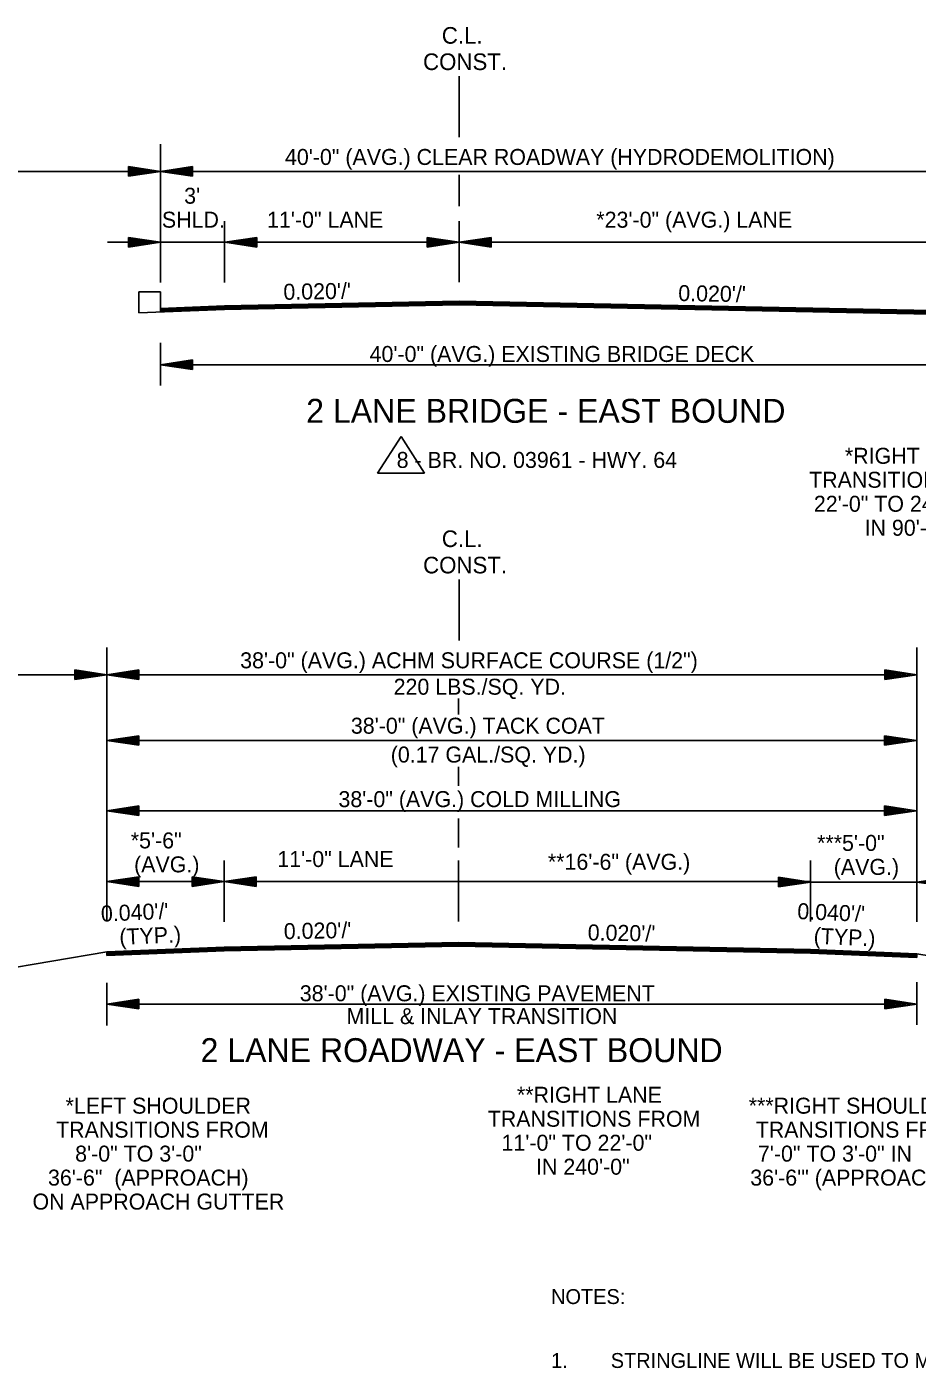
# Model space of a CAD drawing. Extents: x 542112 to 1930787, y -1968972 to 596640.
# Drawn here: x 545011 to 545428, y -1951935 to -1951306 of the extents above; entities that cross this region are included whole.
import ezdxf

# ---------------------------------------------------------------- set-up
doc = ezdxf.new("R2010")
doc.units = 0
for name, color, linetype in [('R_Border', 7, 'Continuous'), ('R_Border Notes', 7, 'Continuous'), ('R_Draft', 7, 'Continuous')]:
    doc.layers.add(name, color=color, linetype=linetype)

msp = doc.modelspace()

# ---------------------------------------------------------------- linework, layer by layer
at = {"layer": 'R_Border'}
for p, q in [((545073.38, -1951430.3), (545063.21, -1951430.3)), ((545063.21, -1951430.3), (545063.21, -1951440.11)), ((545073.38, -1951439.73), (545073.38, -1951430.3)), ((545186.15, -1951498.09), (545175.11, -1951515.4)), ((545197.19, -1951515.4), (545186.15, -1951498.09)), ((545175.11, -1951515.4), (545197.19, -1951515.4))]:
    msp.add_line(p, q, dxfattribs=at)
at = {"layer": 'R_Draft'}
for p, q in [((545213.38, -1951357.67), (545213.38, -1951329.02)), ((545073.38, -1951360.97), (545073.38, -1951425.86)), ((544727.98, -1951373.73), (545073.38, -1951373.73)), ((545058.38, -1951371.48), (545073.38, -1951373.73)), ((545058.38, -1951371.48), (545058.38, -1951375.98)), ((545058.38, -1951371.86), (545070.87, -1951373.73)), ((545058.38, -1951372.24), (545068.29, -1951373.73)), ((545058.38, -1951372.61), (545065.8, -1951373.73)), ((545058.38, -1951373), (545063.25, -1951373.73)), ((545058.38, -1951373.38), (545060.75, -1951373.73)), ((545058.38, -1951375.98), (545073.38, -1951373.73)), ((545058.38, -1951374.47), (545063.25, -1951373.73)), ((545058.38, -1951375.22), (545068.29, -1951373.73)), ((545058.38, -1951375.61), (545070.87, -1951373.73)), ((545058.38, -1951374.85), (545065.8, -1951373.73)), ((545058.38, -1951374.08), (545060.75, -1951373.73)), ((545088.38, -1951371.48), (545073.38, -1951373.73)), ((545088.38, -1951375.98), (545073.38, -1951373.73)), ((545073.38, -1951373.73), (545473.38, -1951373.73)), ((545088.38, -1951371.86), (545075.88, -1951373.73)), ((545088.38, -1951375.61), (545075.88, -1951373.73)), ((545088.38, -1951372.24), (545078.46, -1951373.73)), ((545088.38, -1951375.22), (545078.46, -1951373.73)), ((545088.38, -1951372.61), (545080.96, -1951373.73)), ((545088.38, -1951374.85), (545080.96, -1951373.73)), ((545088.38, -1951373), (545083.5, -1951373.73)), ((545088.38, -1951374.46), (545083.5, -1951373.73)), ((545088.38, -1951373.38), (545086.01, -1951373.73)), ((545088.38, -1951374.08), (545086.01, -1951373.73)), ((545088.38, -1951375.98), (545088.38, -1951371.48)), ((545213.38, -1951390.12), (545213.38, -1951375.32)), ((545103.38, -1951425.86), (545103.38, -1951397.13)), ((545213.38, -1951425.69), (545213.38, -1951397.13)), ((545103.38, -1951407.03), (545048.38, -1951407.03)), ((545058.38, -1951404.78), (545073.38, -1951407.03)), ((545058.38, -1951404.78), (545058.38, -1951409.28)), ((545058.38, -1951405.15), (545070.87, -1951407.03)), ((545058.38, -1951405.53), (545068.29, -1951407.03)), ((545058.38, -1951405.91), (545065.8, -1951407.03)), ((545058.38, -1951406.3), (545063.25, -1951407.03)), ((545058.38, -1951406.67), (545060.75, -1951407.03)), ((545058.38, -1951409.28), (545073.38, -1951407.03)), ((545058.38, -1951407.76), (545063.25, -1951407.03)), ((545058.38, -1951408.52), (545068.29, -1951407.03)), ((545058.38, -1951408.9), (545070.87, -1951407.03)), ((545058.38, -1951408.14), (545065.8, -1951407.03)), ((545058.38, -1951407.38), (545060.75, -1951407.03)), ((545213.38, -1951407.03), (545103.38, -1951407.03)), ((545118.5, -1951404.78), (545103.5, -1951407.03)), ((545118.5, -1951409.28), (545103.5, -1951407.03)), ((545118.5, -1951405.15), (545106.01, -1951407.03)), ((545118.5, -1951408.9), (545106.01, -1951407.03)), ((545118.5, -1951405.53), (545108.59, -1951407.03)), ((545118.5, -1951408.52), (545108.59, -1951407.03)), ((545118.5, -1951405.91), (545111.09, -1951407.03)), ((545118.5, -1951408.14), (545111.09, -1951407.03)), ((545118.5, -1951406.29), (545113.63, -1951407.03)), ((545118.5, -1951407.75), (545113.63, -1951407.03)), ((545118.5, -1951406.67), (545116.13, -1951407.03)), ((545118.5, -1951407.38), (545116.13, -1951407.03)), ((545118.5, -1951409.28), (545118.5, -1951404.78)), ((545198.38, -1951404.78), (545213.38, -1951407.03)), ((545198.38, -1951404.78), (545198.38, -1951409.28)), ((545198.38, -1951405.15), (545210.87, -1951407.03)), ((545198.38, -1951405.53), (545208.29, -1951407.03)), ((545198.38, -1951405.91), (545205.8, -1951407.03)), ((545198.38, -1951406.3), (545203.25, -1951407.03)), ((545198.38, -1951406.67), (545200.75, -1951407.03)), ((545198.38, -1951409.28), (545213.38, -1951407.03)), ((545198.38, -1951407.76), (545203.25, -1951407.03)), ((545198.38, -1951408.52), (545208.29, -1951407.03)), ((545198.38, -1951408.9), (545210.87, -1951407.03)), ((545198.38, -1951408.14), (545205.8, -1951407.03)), ((545198.38, -1951407.38), (545200.75, -1951407.03)), ((545228.38, -1951404.78), (545213.38, -1951407.03)), ((545443.38, -1951407.03), (545213.38, -1951407.03)), ((545228.38, -1951409.28), (545213.38, -1951407.03)), ((545228.38, -1951405.15), (545215.88, -1951407.03)), ((545228.38, -1951408.9), (545215.88, -1951407.03)), ((545228.38, -1951405.53), (545218.46, -1951407.03)), ((545228.38, -1951408.52), (545218.46, -1951407.03)), ((545228.38, -1951405.91), (545220.96, -1951407.03)), ((545228.38, -1951408.14), (545220.96, -1951407.03)), ((545228.38, -1951406.29), (545223.5, -1951407.03)), ((545228.38, -1951407.75), (545223.5, -1951407.03)), ((545228.38, -1951406.67), (545226.01, -1951407.03)), ((545228.38, -1951407.38), (545226.01, -1951407.03)), ((545228.38, -1951409.28), (545228.38, -1951404.78)), ((545103.38, -1951438.5), (545063.21, -1951440.11)), ((545103.38, -1951436.83), (545073.38, -1951438.03)), ((545103.38, -1951437.13), (545073.38, -1951438.33)), ((545103.38, -1951437.43), (545073.38, -1951438.63)), ((545103.38, -1951437.73), (545073.38, -1951438.93)), ((545103.38, -1951438.03), (545073.38, -1951439.23)), ((545103.38, -1951438.33), (545073.38, -1951439.53)), ((545213.38, -1951434.63), (545103.38, -1951436.83)), ((545213.38, -1951434.93), (545103.38, -1951437.13)), ((545213.38, -1951435.23), (545103.38, -1951437.43)), ((545213.38, -1951435.53), (545103.38, -1951437.73)), ((545213.38, -1951435.83), (545103.38, -1951438.03)), ((545213.38, -1951436.13), (545103.38, -1951438.33)), ((545213.38, -1951436.3), (545103.38, -1951438.5)), ((545213.38, -1951434.63), (545453.31, -1951439.43)), ((545213.38, -1951434.93), (545453.31, -1951439.73)), ((545213.38, -1951435.23), (545453.31, -1951440.03)), ((545213.38, -1951435.53), (545453.31, -1951440.33)), ((545213.38, -1951435.83), (545453.31, -1951440.63)), ((545213.38, -1951436.13), (545453.31, -1951440.93)), ((545213.38, -1951436.3), (545453.31, -1951441.1)), ((545073.38, -1951454.24), (545073.38, -1951474.24)), ((545088.37, -1951462.24), (545073.37, -1951464.49)), ((545088.37, -1951462.62), (545075.87, -1951464.49)), ((545088.37, -1951463), (545078.45, -1951464.49)), ((545088.37, -1951463.37), (545080.95, -1951464.49)), ((545088.37, -1951463.76), (545083.49, -1951464.49)), ((545088.37, -1951466.74), (545088.37, -1951462.24)), ((545088.37, -1951466.74), (545073.37, -1951464.49)), ((545073.38, -1951464.49), (545473.31, -1951464.49)), ((545088.37, -1951466.37), (545075.87, -1951464.49)), ((545088.37, -1951465.98), (545078.45, -1951464.49)), ((545088.37, -1951465.61), (545080.95, -1951464.49)), ((545088.37, -1951465.22), (545083.49, -1951464.49)), ((545088.37, -1951464.14), (545086, -1951464.49)), ((545088.37, -1951464.84), (545086, -1951464.49)), ((545213.38, -1951593.87), (545213.38, -1951565.22)), ((545048.18, -1951597.18), (545048.18, -1951725.69)), ((545428.18, -1951597.18), (545428.18, -1951725.86)), ((545033.18, -1951607.68), (545048.18, -1951609.93)), ((545033.18, -1951607.68), (545033.18, -1951612.18)), ((545033.18, -1951607.68), (545048.18, -1951609.93)), ((545033.18, -1951607.68), (545033.18, -1951612.18)), ((545033.18, -1951608.06), (545045.67, -1951609.93)), ((545033.18, -1951608.06), (545045.67, -1951609.93)), ((545033.18, -1951608.44), (545043.09, -1951609.93)), ((545033.18, -1951608.44), (545043.09, -1951609.93)), ((545063.18, -1951607.68), (545048.18, -1951609.93)), ((545063.18, -1951608.06), (545050.68, -1951609.93)), ((545063.18, -1951608.44), (545053.26, -1951609.93)), ((545063.18, -1951607.68), (545063.18, -1951612.18)), ((545413.18, -1951607.68), (545428.18, -1951609.93)), ((545413.18, -1951612.18), (545413.18, -1951607.68)), ((545413.18, -1951608.06), (545425.67, -1951609.93)), ((545413.18, -1951608.44), (545423.09, -1951609.93)), ((544778.18, -1951609.93), (545048.18, -1951609.93)), ((545033.18, -1951608.82), (545040.6, -1951609.93)), ((545033.18, -1951608.82), (545040.6, -1951609.93)), ((545033.18, -1951609.21), (545038.05, -1951609.93)), ((545033.18, -1951609.21), (545038.05, -1951609.93)), ((545033.18, -1951609.58), (545035.55, -1951609.93)), ((545033.18, -1951609.58), (545035.55, -1951609.93)), ((545033.18, -1951612.18), (545048.18, -1951609.93)), ((545033.18, -1951610.67), (545038.05, -1951609.93)), ((545033.18, -1951611.43), (545043.09, -1951609.93)), ((545033.18, -1951611.81), (545045.67, -1951609.93)), ((545033.18, -1951611.05), (545040.6, -1951609.93)), ((545033.18, -1951610.29), (545035.55, -1951609.93)), ((545033.18, -1951612.18), (545048.18, -1951609.93)), ((545033.18, -1951610.67), (545038.05, -1951609.93)), ((545033.18, -1951611.43), (545043.09, -1951609.93)), ((545033.18, -1951611.81), (545045.67, -1951609.93)), ((545033.18, -1951611.05), (545040.6, -1951609.93)), ((545033.18, -1951610.29), (545035.55, -1951609.93)), ((545418.18, -1951609.93), (545048.18, -1951609.93)), ((545063.18, -1951612.18), (545048.18, -1951609.93)), ((545063.18, -1951611.81), (545050.68, -1951609.93)), ((545063.18, -1951611.43), (545053.26, -1951609.93)), ((545063.18, -1951608.82), (545055.76, -1951609.93)), ((545063.18, -1951611.05), (545055.76, -1951609.93)), ((545063.18, -1951609.21), (545058.3, -1951609.93)), ((545063.18, -1951610.67), (545058.3, -1951609.93)), ((545063.18, -1951609.58), (545060.81, -1951609.93)), ((545063.18, -1951610.29), (545060.81, -1951609.93)), ((545413.18, -1951608.82), (545420.6, -1951609.93)), ((545413.18, -1951609.2), (545418.05, -1951609.93)), ((545413.18, -1951609.58), (545415.55, -1951609.93)), ((545413.18, -1951612.18), (545428.18, -1951609.93)), ((545413.18, -1951610.66), (545418.05, -1951609.93)), ((545413.18, -1951611.43), (545423.09, -1951609.93)), ((545413.18, -1951611.81), (545425.67, -1951609.93)), ((545413.18, -1951611.05), (545420.6, -1951609.93)), ((545413.18, -1951610.29), (545415.55, -1951609.93)), ((545213.18, -1951621.16), (545213.18, -1951628.53)), ((545063.18, -1951638.55), (545048.18, -1951640.8)), ((545063.18, -1951638.93), (545050.68, -1951640.8)), ((545063.18, -1951639.31), (545053.26, -1951640.8)), ((545063.18, -1951639.68), (545055.76, -1951640.8)), ((545063.18, -1951640.07), (545058.3, -1951640.8)), ((545063.18, -1951643.05), (545063.18, -1951638.55)), ((545412.98, -1951638.55), (545427.98, -1951640.8)), ((545412.98, -1951638.55), (545412.98, -1951643.05)), ((545412.98, -1951638.93), (545425.47, -1951640.8)), ((545412.98, -1951639.31), (545422.89, -1951640.8)), ((545412.98, -1951639.68), (545420.4, -1951640.8)), ((545412.98, -1951640.07), (545417.85, -1951640.8)), ((545418.18, -1951640.8), (545048.18, -1951640.8)), ((545063.18, -1951643.05), (545048.18, -1951640.8)), ((545063.18, -1951642.68), (545050.68, -1951640.8)), ((545063.18, -1951642.29), (545053.26, -1951640.8)), ((545063.18, -1951641.92), (545055.76, -1951640.8)), ((545063.18, -1951641.53), (545058.3, -1951640.8)), ((545063.18, -1951640.45), (545060.81, -1951640.8)), ((545063.18, -1951641.15), (545060.81, -1951640.8)), ((545412.98, -1951640.45), (545415.35, -1951640.8)), ((545412.98, -1951643.05), (545427.98, -1951640.8)), ((545412.98, -1951641.54), (545417.85, -1951640.8)), ((545412.98, -1951642.29), (545422.89, -1951640.8)), ((545412.98, -1951642.68), (545425.47, -1951640.8)), ((545412.98, -1951641.92), (545420.4, -1951640.8)), ((545412.98, -1951641.15), (545415.35, -1951640.8)), ((545213.18, -1951653.15), (545213.18, -1951662.11)), ((545063.18, -1951671.48), (545048.18, -1951673.73)), ((545063.18, -1951675.98), (545063.18, -1951671.48)), ((545412.98, -1951671.48), (545427.98, -1951673.73)), ((545412.98, -1951671.48), (545412.98, -1951675.98)), ((545063.18, -1951675.98), (545048.18, -1951673.73)), ((545418.18, -1951673.73), (545048.18, -1951673.73)), ((545063.18, -1951671.86), (545050.68, -1951673.73)), ((545063.18, -1951675.61), (545050.68, -1951673.73)), ((545063.18, -1951672.24), (545053.26, -1951673.73)), ((545063.18, -1951675.22), (545053.26, -1951673.73)), ((545063.18, -1951672.61), (545055.76, -1951673.73)), ((545063.18, -1951674.85), (545055.76, -1951673.73)), ((545063.18, -1951673), (545058.3, -1951673.73)), ((545063.18, -1951674.46), (545058.3, -1951673.73)), ((545063.18, -1951673.38), (545060.81, -1951673.73)), ((545063.18, -1951674.08), (545060.81, -1951673.73)), ((545213.18, -1951677.36), (545213.18, -1951691)), ((545412.98, -1951671.86), (545425.47, -1951673.73)), ((545412.98, -1951672.24), (545422.89, -1951673.73)), ((545412.98, -1951672.61), (545420.4, -1951673.73)), ((545412.98, -1951673), (545417.85, -1951673.73)), ((545412.98, -1951673.38), (545415.35, -1951673.73)), ((545412.98, -1951675.98), (545427.98, -1951673.73)), ((545412.98, -1951674.47), (545417.85, -1951673.73)), ((545412.98, -1951675.22), (545422.89, -1951673.73)), ((545412.98, -1951675.61), (545425.47, -1951673.73)), ((545412.98, -1951674.85), (545420.4, -1951673.73)), ((545412.98, -1951674.08), (545415.35, -1951673.73)), ((545103.18, -1951725.86), (545103.18, -1951697.13)), ((545213.18, -1951725.69), (545213.18, -1951697.13)), ((545378.18, -1951725.69), (545378.18, -1951697.13)), ((545063.18, -1951704.78), (545048.18, -1951707.03)), ((545103.18, -1951707.03), (545048.18, -1951707.03)), ((545063.18, -1951709.28), (545048.18, -1951707.03)), ((545063.18, -1951705.15), (545050.68, -1951707.03)), ((545063.18, -1951708.9), (545050.68, -1951707.03)), ((545063.18, -1951705.53), (545053.26, -1951707.03)), ((545063.18, -1951708.52), (545053.26, -1951707.03)), ((545063.18, -1951705.91), (545055.76, -1951707.03)), ((545063.18, -1951708.14), (545055.76, -1951707.03)), ((545063.18, -1951706.29), (545058.3, -1951707.03)), ((545063.18, -1951707.75), (545058.3, -1951707.03)), ((545063.18, -1951706.67), (545060.81, -1951707.03)), ((545063.18, -1951707.38), (545060.81, -1951707.03)), ((545063.18, -1951709.28), (545063.18, -1951704.78)), ((545088.18, -1951704.78), (545103.18, -1951707.03)), ((545088.18, -1951704.78), (545088.18, -1951709.28)), ((545088.18, -1951705.15), (545100.67, -1951707.03)), ((545088.18, -1951705.53), (545098.09, -1951707.03)), ((545088.18, -1951705.91), (545095.6, -1951707.03)), ((545088.18, -1951706.3), (545093.05, -1951707.03)), ((545088.18, -1951706.67), (545090.55, -1951707.03)), ((545088.18, -1951709.28), (545103.18, -1951707.03)), ((545088.18, -1951707.76), (545093.05, -1951707.03)), ((545088.18, -1951708.52), (545098.09, -1951707.03)), ((545088.18, -1951708.9), (545100.67, -1951707.03)), ((545088.18, -1951708.14), (545095.6, -1951707.03)), ((545088.18, -1951707.38), (545090.55, -1951707.03)), ((545118.18, -1951704.78), (545103.18, -1951707.03)), ((545213.18, -1951707.03), (545103.18, -1951707.03)), ((545118.18, -1951709.28), (545103.18, -1951707.03)), ((545118.18, -1951705.15), (545105.68, -1951707.03)), ((545118.18, -1951708.9), (545105.68, -1951707.03)), ((545118.18, -1951705.53), (545108.26, -1951707.03)), ((545118.18, -1951708.52), (545108.26, -1951707.03)), ((545118.18, -1951705.91), (545110.76, -1951707.03)), ((545118.18, -1951708.14), (545110.76, -1951707.03)), ((545118.18, -1951706.29), (545113.3, -1951707.03)), ((545118.18, -1951707.75), (545113.3, -1951707.03)), ((545118.18, -1951706.67), (545115.81, -1951707.03)), ((545118.18, -1951707.38), (545115.81, -1951707.03)), ((545118.18, -1951709.28), (545118.18, -1951704.78)), ((545213.18, -1951707.03), (545378.18, -1951707.03)), ((545363.18, -1951704.95), (545378.18, -1951707.2)), ((545363.18, -1951704.95), (545363.18, -1951709.45)), ((545363.18, -1951705.32), (545375.67, -1951707.2)), ((545363.18, -1951705.7), (545373.09, -1951707.2)), ((545363.18, -1951706.08), (545370.6, -1951707.2)), ((545363.18, -1951706.47), (545368.05, -1951707.2)), ((545363.18, -1951706.84), (545365.55, -1951707.2)), ((545363.18, -1951709.45), (545378.18, -1951707.2)), ((545363.18, -1951707.93), (545368.05, -1951707.2)), ((545363.18, -1951708.69), (545373.09, -1951707.2)), ((545363.18, -1951709.07), (545375.67, -1951707.2)), ((545363.18, -1951708.31), (545370.6, -1951707.2)), ((545363.18, -1951707.55), (545365.55, -1951707.2)), ((545378.18, -1951707.2), (545428.18, -1951707.2)), ((545443.18, -1951704.95), (545428.18, -1951707.2)), ((545443.18, -1951709.45), (545428.18, -1951707.2)), ((545428.18, -1951707.2), (545453.18, -1951707.2)), ((545048.18, -1951740.03), (544913.18, -1951762.53)), ((545103.18, -1951737.83), (545048.18, -1951740.03)), ((545103.18, -1951738.13), (545048.18, -1951740.33)), ((545103.18, -1951738.43), (545048.18, -1951740.63)), ((545103.18, -1951738.73), (545048.18, -1951740.93)), ((545103.18, -1951739.03), (545048.18, -1951741.23)), ((545103.18, -1951739.33), (545048.18, -1951741.53)), ((545103.18, -1951739.5), (545048.18, -1951741.7)), ((545048.18, -1951741.7), (545048.18, -1951740.03)), ((545213.18, -1951735.63), (545103.18, -1951737.83)), ((545213.18, -1951735.93), (545103.18, -1951738.13)), ((545213.18, -1951736.23), (545103.18, -1951738.43)), ((545213.18, -1951736.53), (545103.18, -1951738.73)), ((545213.18, -1951736.83), (545103.18, -1951739.03)), ((545213.18, -1951737.13), (545103.18, -1951739.33)), ((545213.18, -1951737.3), (545103.18, -1951739.5)), ((545213.18, -1951735.63), (545378.18, -1951738.93)), ((545213.18, -1951735.93), (545378.18, -1951739.23)), ((545213.18, -1951736.23), (545378.18, -1951739.53)), ((545213.18, -1951736.53), (545378.18, -1951739.83)), ((545213.18, -1951736.83), (545378.18, -1951740.13)), ((545213.18, -1951737.13), (545378.18, -1951740.43)), ((545213.18, -1951737.3), (545378.18, -1951740.6)), ((545378.18, -1951738.93), (545428.18, -1951740.93)), ((545378.18, -1951739.23), (545428.18, -1951741.23)), ((545378.18, -1951739.53), (545428.18, -1951741.53)), ((545378.18, -1951739.83), (545428.18, -1951741.83)), ((545378.18, -1951740.13), (545428.18, -1951742.13)), ((545378.18, -1951740.43), (545428.18, -1951742.43)), ((545378.18, -1951740.6), (545428.18, -1951742.6)), ((545428.18, -1951740.93), (545531.86, -1951758.21)), ((545428.18, -1951742.6), (545428.18, -1951740.93)), ((545048.18, -1951754.57), (545048.18, -1951774.57)), ((545428.18, -1951754.24), (545428.18, -1951774.24)), ((545063.18, -1951762.24), (545048.18, -1951764.49)), ((545418.18, -1951764.49), (545048.18, -1951764.49)), ((545063.18, -1951766.74), (545048.18, -1951764.49)), ((545063.18, -1951762.62), (545050.68, -1951764.49)), ((545063.18, -1951766.37), (545050.68, -1951764.49)), ((545063.18, -1951763), (545053.26, -1951764.49)), ((545063.18, -1951765.98), (545053.26, -1951764.49)), ((545063.18, -1951763.37), (545055.76, -1951764.49)), ((545063.18, -1951765.61), (545055.76, -1951764.49)), ((545063.18, -1951763.76), (545058.3, -1951764.49)), ((545063.18, -1951765.23), (545058.3, -1951764.49)), ((545063.18, -1951764.14), (545060.81, -1951764.49)), ((545063.18, -1951764.84), (545060.81, -1951764.49)), ((545063.18, -1951762.24), (545063.18, -1951766.74)), ((545413.19, -1951762.24), (545428.19, -1951764.49)), ((545413.19, -1951766.74), (545413.19, -1951762.24)), ((545413.19, -1951762.62), (545425.69, -1951764.49)), ((545413.19, -1951763), (545423.11, -1951764.49)), ((545413.19, -1951763.37), (545420.61, -1951764.49)), ((545413.19, -1951763.76), (545418.07, -1951764.49)), ((545413.19, -1951764.14), (545415.56, -1951764.49)), ((545413.19, -1951766.74), (545428.19, -1951764.49)), ((545413.19, -1951765.22), (545418.07, -1951764.49)), ((545413.19, -1951765.98), (545423.11, -1951764.49)), ((545413.19, -1951766.37), (545425.69, -1951764.49)), ((545413.19, -1951765.61), (545420.61, -1951764.49)), ((545413.19, -1951764.84), (545415.56, -1951764.49))]:
    msp.add_line(p, q, dxfattribs=at)

# ---------------------------------------------------------------- texts
at = {"layer": 'R_Border Notes'}
for s, p in [('NOTES: ', (545256.54, -1951905.23)), ('1.', (545256.54, -1951935.23)), ('STRINGLINE WILL BE USED TO MAINTAIN A UNIFORM HORIZONTAL ALIGNMENT.', (545284.54, -1951935.23))]:
    msp.add_text(s, height=7, dxfattribs=at).set_placement(p)
at = {"layer": 'R_Draft'}
for s, height, p in [('C.L.', 7.8, (545205.28, -1951313.82)), ('CONST.', 7.8, (545196.49, -1951326.19)), ('40\'-0" (AVG.) CLEAR ROADWAY (HYDRODEMOLITION)', 7.5, (545131.71, -1951370.72)), ("3' ", 7.5, (545084.42, -1951388.91)), ('SHLD.', 7.5, (545073.97, -1951400.16)), ('11\'-0" LANE', 7.5, (545123.32, -1951400.16)), ('*23\'-0" (AVG.) LANE', 7.5, (545277.77, -1951400.16)), ('40\'-0" (AVG.) EXISTING BRIDGE DECK', 7.5, (545171.41, -1951463.17)), ('2 LANE BRIDGE - EAST BOUND', 11.25, (545141.65, -1951491.73)), ('8 - BR. NO. 03961 - HWY. 64', 7.5, (545184.11, -1951512.89)), ('*RIGHT LANE', 7.5, (545394.38, -1951510.96)), ('TRANSITIONS FROM ', 7.5, (545377.61, -1951522.21)), ('22\'-0" TO 24\'-0"', 7.5, (545379.83, -1951533.46)), ('IN 90\'-0"', 7.5, (545403.63, -1951544.71)), ('C.L.', 7.8, (545205.29, -1951550.02)), ('CONST.', 7.8, (545196.51, -1951562.39)), ('38\'-0" (AVG.) ACHM SURFACE COURSE (1/2")', 7.5, (545110.7, -1951606.92)), ('220 LBS./SQ. YD. ', 7.5, (545182.69, -1951619.31)), ('38\'-0" (AVG.) TACK COAT', 7.5, (545162.64, -1951637.6)), ('(0.17 GAL./SQ. YD.)', 7.5, (545181.33, -1951651.14)), ('38\'-0" (AVG.) COLD MILLING', 7.5, (545156.79, -1951672.06)), ('*5\'-6"', 7.5, (545059.38, -1951691.42)), ('***5\'-0"', 7.5, (545381.33, -1951692.61)), ('(AVG.)', 7.5, (545060.94, -1951702.67)), ('11\'-0" LANE', 7.5, (545128.12, -1951700.16)), ('**16\'-6" (AVG.)', 7.5, (545255.05, -1951701.47)), ('(AVG.)', 7.5, (545389.16, -1951703.86)), ('38\'-0" (AVG.) EXISTING PAVEMENT', 7.5, (545138.66, -1951763.17)), ('MILL & INLAY TRANSITION', 7.5, (545160.57, -1951773.89)), ('2 LANE ROADWAY - EAST BOUND', 11.25, (545092.11, -1951791.73)), ('**RIGHT LANE', 7.5, (545240.54, -1951810.79)), ('*LEFT SHOULDER', 7.5, (545028.79, -1951815.91)), ('***RIGHT SHOULDER', 7.5, (545349.26, -1951815.91)), ('TRANSITIONS FROM ', 7.5, (545226.84, -1951822.04)), ('TRANSITIONS FROM ', 7.5, (545024.33, -1951827.16)), ('TRANSITIONS FROM ', 7.5, (545352.54, -1951827.16)), ('11\'-0" TO 22\'-0"', 7.5, (545233.3, -1951833.29)), ('8\'-0" TO 3\'-0"', 7.5, (545033.28, -1951838.41)), ('7\'-0" TO 3\'-0" IN', 7.5, (545353.58, -1951838.41)), ('IN 240\'-0"', 7.5, (545249.48, -1951844.54)), ('36\'-6"  (APPROACH)', 7.5, (545020.55, -1951849.66)), ('36\'-6\'" (APPROACH)', 7.5, (545350, -1951849.66)), ('ON APPROACH GUTTER', 7.5, (545013.26, -1951860.91))]:
    msp.add_text(s, height=height, dxfattribs=at).set_placement(p)
for s, rotation, p in [("0.020'/'", 0.97192, (545131.03, -1951434.02)), ("0.020'/'", 359.02808, (545316.17, -1951434.56)), ("  0.040'/'", 2.44797, (545039.95, -1951726.06)), ("  0.040'/'", 357.55203, (545366.38, -1951724.32)), (' (TYP.)', 2.44797, (545051.37, -1951736.83)), ("0.020'/'", 0.97192, (545131.22, -1951734.02)), ("0.020'/'", 359.02808, (545273.69, -1951734.56)), (' (TYP.)', 357.55203, (545376.84, -1951736.02))]:
    msp.add_text(s, height=7.5, rotation=rotation, dxfattribs=at).set_placement(p)

doc.saveas('drawing.dxf')
